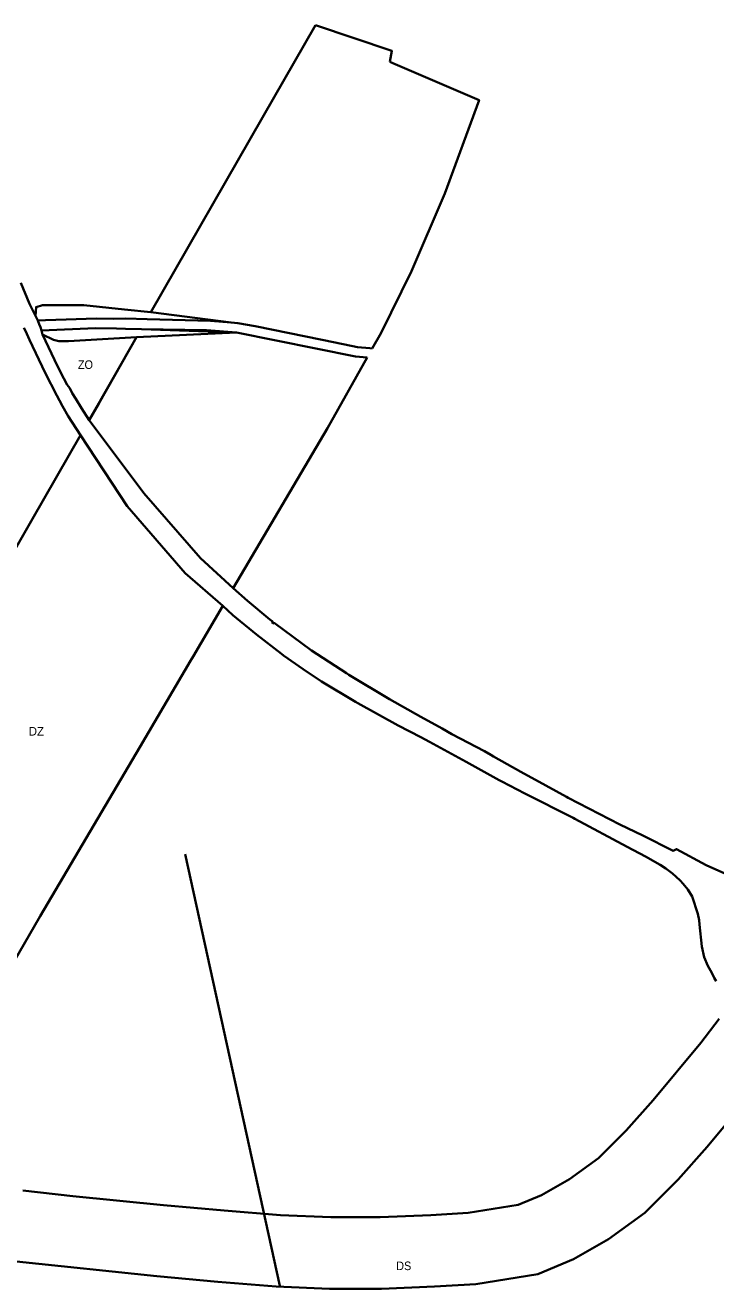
# Model space of a CAD drawing. Extents: x -650276 to -642489, y -1074311 to -1066720.
# Drawn here: x -647696 to -646730, y -1069094 to -1067326 of the extents above; entities that cross this region are included whole.
import ezdxf

# ---------------------------------------------------------------- set-up
doc = ezdxf.new("R2010")
doc.units = 0
doc.header["$LTSCALE"] = 4.8
for name, color, linetype, lineweight in [('24', 7, 'Continuous', 35), ('25', 7, 'Continuous', 35), ('42', 7, 'Continuous', 35), ('54', 7, 'Continuous', 35)]:
    doc.layers.add(name, color=color, linetype=linetype, lineweight=lineweight)
doc.layers.add('62', color=7, linetype='Continuous')

msp = doc.modelspace()

# ---------------------------------------------------------------- linework, layer by layer
at = {"layer": '24'}
for points in [[(-647606.818, -1067879.061), (-647617.25, -1067861.95), (-647625.37, -1067848.86), (-647630.3, -1067841.02), (-647633.69, -1067834.31), (-647637.21, -1067829.29), (-647642.29, -1067820.76), (-647650.8, -1067803.28), (-647672.05, -1067758.98), (-647673.47, -1067753.48), (-647673.47, -1067753.48), (-647674.67, -1067748.73), (-647676.47, -1067744.5), (-647678.66, -1067739.38), (-647681.91, -1067732.74), (-647690.09, -1067716.05), (-647702.04, -1067686.86)], [(-647697.85, -1067749.46), (-647695.71, -1067753.9), (-647690.19, -1067766.37), (-647668.13, -1067812.76), (-647651.94, -1067844.36), (-647648.33, -1067851.17), (-647643.83, -1067859.13), (-647635.77, -1067873.43), (-647618.773, -1067899.914)], [(-647405.026, -1068113.904), (-647451.024, -1068071.886), (-647530.038, -1067980.839), (-647606.818, -1067879.061)], [(-647618.773, -1067899.914), (-647553.628, -1067999.427), (-647472.338, -1068093.096), (-647419.713, -1068138.871)], [(-646686.84, -1068526.89), (-646743.69, -1068501.76), (-646785.05, -1068479.12), (-646787.55, -1068480.36), (-646789.49, -1068481.31), (-646832.29, -1068460.04), (-646864.48, -1068444.64), (-646936.47, -1068407.23), (-646938.95, -1068405.8), (-646967.64, -1068390), (-647002.71, -1068371.09), (-647040.77, -1068349.4), (-647044.93, -1068347.08), (-647053.75, -1068342.11), (-647099.2, -1068318.27), (-647112.813, -1068310.564), (-647142.41, -1068293.81), (-647186.26, -1068269.45), (-647243.39, -1068235.26), (-647246.8, -1068233.08), (-647295.47, -1068201.09), (-647347.74, -1068162.54), (-647349.59, -1068163.24), (-647350.6, -1068160.26), (-647353.81, -1068157.67), (-647385.13, -1068131.51), (-647405.026, -1068113.904)], [(-647419.713, -1068138.871), (-647405.71, -1068151.74), (-647372.38, -1068179.01), (-647337.74, -1068205.67), (-647334.62, -1068208.02), (-647307.39, -1068227.44), (-647281.64, -1068244.34), (-647234.11, -1068273.04), (-647230.83, -1068274.93), (-647174.56, -1068306.35), (-647142.788, -1068322.462), (-647130.29, -1068328.8), (-647079.16, -1068357.01), (-647032.91, -1068382.51), (-647029.23, -1068384.46), (-646997.06, -1068401.37), (-646929.56, -1068435.42), (-646927.06, -1068436.66)], [(-646927.06, -1068436.66), (-646854.18, -1068475.8), (-646828.2, -1068489.61), (-646807.82, -1068501.17), (-646799.79, -1068506.39), (-646790.66, -1068513.24), (-646785.34, -1068517.77), (-646779.93, -1068522.9), (-646775.44, -1068527.74), (-646768.95, -1068535.8), (-646763.1, -1068545.18), (-646754.92, -1068569.81), (-646753.35, -1068578.6), (-646752.59, -1068584.55), (-646749.35, -1068615.18), (-646746.32, -1068630.23), (-646740.91, -1068642.34), (-646735.62, -1068652.21), (-646732.25, -1068659.06), (-646729.34, -1068663.94)], [(-646725.374, -1068716.786), (-646751.116, -1068749.975), (-646817.718, -1068830.545), (-646855.506, -1068872.883), (-646894.206, -1068911.595), (-646934.465, -1068940.759), (-646973.61, -1068963.135), (-647006.63, -1068977.08), (-647076.422, -1068988.18), (-647128.674, -1068991.167), (-647199.672, -1068994.255), (-647268.348, -1068994.255), (-647338.816, -1068991.19), (-647417.895, -1068984.986), (-647502.412, -1068977.157), (-647629.424, -1068964.608), (-647699.561, -1068956.635)], [(-647708.401, -1069056.275), (-647511.94, -1069076.703), (-647426.417, -1069084.624), (-647344.902, -1069091.02), (-647270.522, -1069094.255), (-647197.498, -1069094.255), (-647123.648, -1069091.043), (-647065.688, -1069087.73), (-646978.92, -1069073.93), (-646929.186, -1069052.925), (-646880.163, -1069024.903), (-646829.104, -1068987.917), (-646782.784, -1068941.581), (-646741.85, -1068895.719), (-646673.05, -1068812.491)]]:
    msp.add_lwpolyline(points, dxfattribs=at)
for points in [[(-647596.91, -1067736.61), (-647572.33, -1067737.03), (-647555.58, -1067736.71), (-647525.685, -1067737.542), (-647436.72, -1067740.02), (-647408.2, -1067742.37), (-647520.145, -1067727.879), (-647557, -1067724), (-647614, -1067718), (-647643, -1067718), (-647672, -1067718), (-647680.804, -1067720.745), (-647681.91, -1067732.74), (-647678.66, -1067739.38), (-647678.66, -1067739.38), (-647667.76, -1067739.01), (-647638.75, -1067738.03)], [(-647540.208, -1067762.876), (-647400.63, -1067756.19), (-647533.597, -1067751.344), (-647555.67, -1067750.91), (-647568.36, -1067750.7), (-647597.83, -1067750.21), (-647673.47, -1067753.48), (-647672.05, -1067758.98), (-647672.05, -1067758.98), (-647656.469, -1067766.309), (-647649.22, -1067768.38), (-647635.758, -1067768.38)], [(-647540.208, -1067762.876), (-647400.63, -1067756.19), (-647442.6, -1067753.13), (-647533.597, -1067751.344), (-647555.67, -1067750.91), (-647568.36, -1067750.7), (-647597.83, -1067750.21), (-647673.47, -1067753.48), (-647672.05, -1067758.98), (-647672.05, -1067758.98), (-647656.469, -1067766.309), (-647649.22, -1067768.38), (-647635.758, -1067768.38)]]:
    msp.add_lwpolyline(points, close=True, dxfattribs=at)
at = {"layer": '25'}
for points in [[(-647289.924, -1067326.309), (-647364.024, -1067455.561), (-647520.145, -1067727.879), (-647408.2, -1067742.37), (-647398.74, -1067743.15)], [(-647185.93, -1067377.38), (-647183.09, -1067362.16), (-647289.924, -1067326.309)], [(-647210.537, -1067778.594), (-647198.088, -1067756.5), (-647155.592, -1067670.17), (-647108.971, -1067561.55), (-647061.252, -1067430.908), (-647181.878, -1067379.12), (-647185.93, -1067377.38)], [(-647398.74, -1067743.15), (-647374.55, -1067747.34), (-647280.78, -1067766.44), (-647237.91, -1067775.18), (-647231.17, -1067776.55), (-647213.92, -1067778.26), (-647210.537, -1067778.594)], [(-647400.63, -1067756.19), (-647540.208, -1067762.876), (-647593.267, -1067855.425), (-647606.818, -1067879.061)], [(-647217.611, -1067791.149), (-647233.83, -1067789.69), (-647345.11, -1067767.28), (-647400.63, -1067756.19)], [(-647405.026, -1068113.904), (-647273.297, -1067889.981), (-647217.611, -1067791.149)], [(-647606.818, -1067879.061), (-647530.038, -1067980.839), (-647451.024, -1068071.886), (-647405.026, -1068113.904)], [(-647464.94, -1068215.752), (-647461.188, -1068209.373), (-647419.713, -1068138.871), (-647472.338, -1068093.096), (-647553.628, -1067999.427), (-647618.773, -1067899.914), (-647685.819, -1068016.861)], [(-647685.819, -1068016.861), (-647781.346, -1068183.485), (-647791.055, -1068200.507)], [(-647768.02, -1068570.36), (-647770.94, -1068622.47), (-647772.85, -1068656.41), (-647773.08, -1068660.57), (-647773.4, -1068665.71), (-647776.5, -1068714.8), (-647778.95, -1068752.433), (-647675.054, -1068572.919), (-647535.844, -1068336.279), (-647464.94, -1068215.752)]]:
    msp.add_lwpolyline(points, dxfattribs=at)
at = {"layer": '42'}
msp.add_lwpolyline([(-647606.818, -1067879.061), (-647540.208, -1067762.876), (-647635.758, -1067768.38), (-647649.22, -1067768.38), (-647656.469, -1067766.309), (-647672.05, -1067758.98), (-647650.8, -1067803.28), (-647642.29, -1067820.76), (-647637.21, -1067829.29), (-647633.69, -1067834.31), (-647630.3, -1067841.02), (-647625.37, -1067848.86), (-647617.25, -1067861.95)], close=True, dxfattribs=at)
at = {"layer": '54'}
msp.add_line((-647472.11, -1068486.2), (-647340, -1069090), dxfattribs=at)

# ---------------------------------------------------------------- texts
at = {"layer": '62', "width": 0.95}
for s, p in [('ZO', (-647622.423, -1067807.188)), ('DS', (-647177.118, -1069068.225))]:
    msp.add_text(s, height=12, dxfattribs=at).set_placement(p)
at = {"layer": '62'}
msp.add_text('DZ', height=12, dxfattribs=at).set_placement((-647691.118, -1068320.225))

doc.saveas('drawing.dxf')
